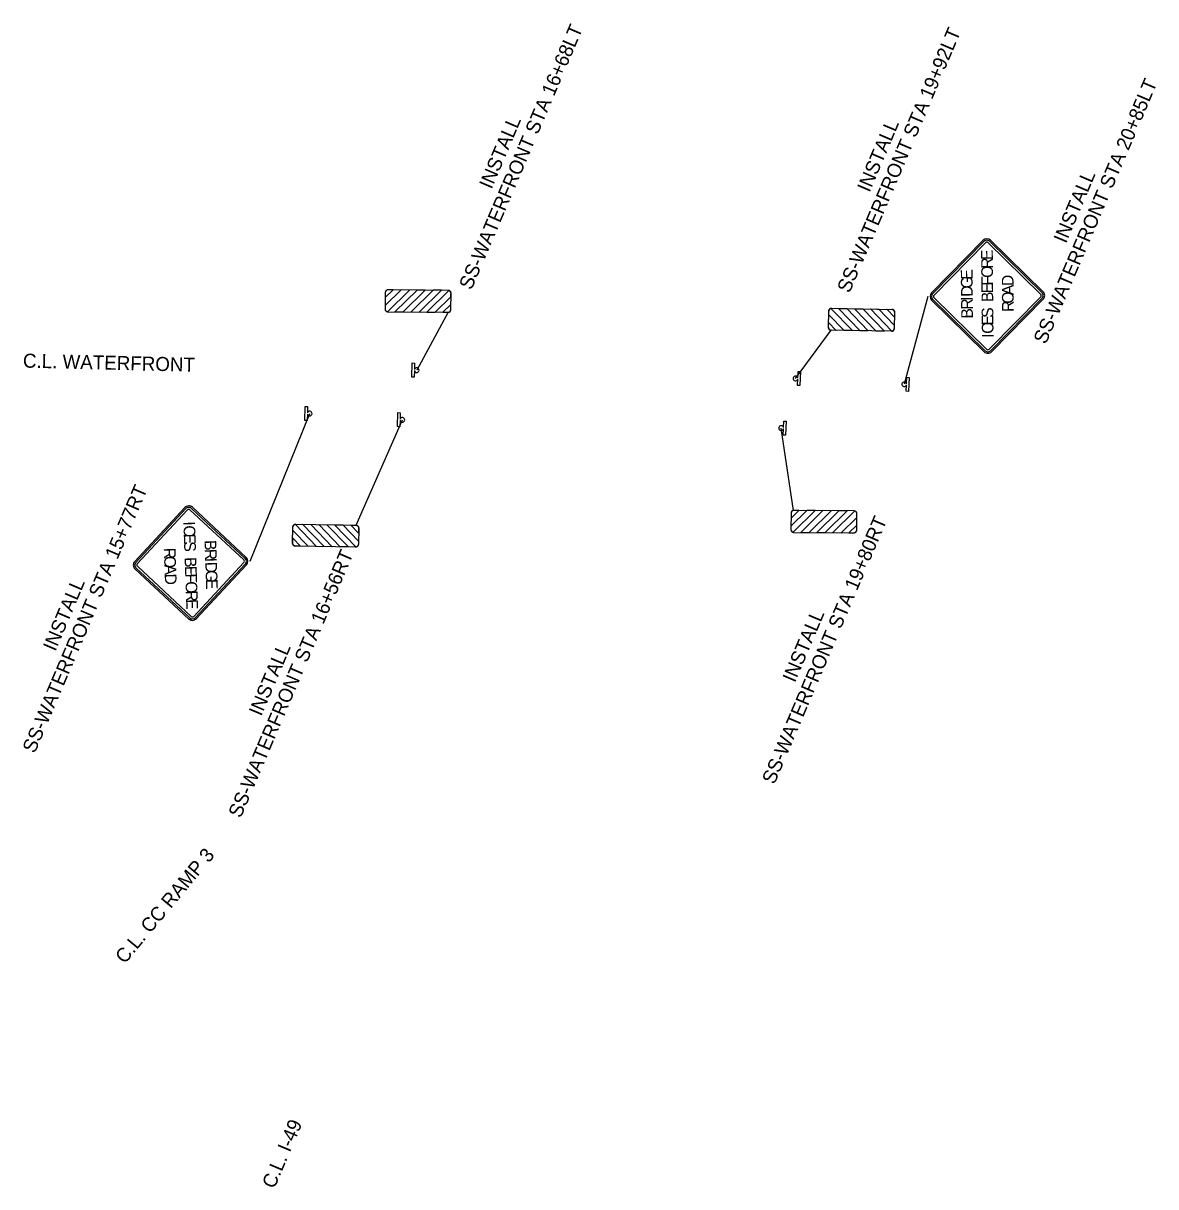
# Model space of a CAD drawing. Extents: x 639753 to 654136, y 407791 to 434220.
# Drawn here: x 652998 to 653966, y 407791 to 408786 of the extents above; entities that cross this region are included whole.
import ezdxf

# ---------------------------------------------------------------- set-up
doc = ezdxf.new("R2010")
doc.units = 0
for name, color, linetype in [('C-TRAF-SYMB', 7, 'Continuous'), ('P_SIGN_SR', 7, 'Continuous'), ('R_Anno_Text', 7, 'Continuous'), ('S_SIGN', 7, 'Continuous')]:
    doc.layers.add(name, color=color, linetype=linetype)

msp = doc.modelspace()

# ---------------------------------------------------------------- linework, layer by layer
at = {"layer": 'C-TRAF-SYMB'}
for p, q in [((653660.21, 408483.12), (653660.45, 408488.63)), ((653660.45, 408488.63), (653662.45, 408488.55)), ((653662.45, 408488.55), (653661.92, 408476.56)), ((653659.93, 408476.65), (653660.17, 408482.21)), ((653661.92, 408476.56), (653659.93, 408476.65)), ((653660.17, 408482.21), (653660.12, 408482.21)), ((653660.15, 408483.12), (653660.21, 408483.12)), ((653752.92, 408471.66), (653753.16, 408477.23)), ((653753.16, 408477.23), (653753.12, 408477.23)), ((653753.15, 408478.13), (653753.2, 408478.13)), ((653753.2, 408478.13), (653753.45, 408483.65)), ((653753.45, 408483.65), (653755.44, 408483.56)), ((653755.44, 408483.56), (653754.92, 408471.57)), ((653754.92, 408471.57), (653752.92, 408471.66)), ((653238.55, 408446.76), (653238.75, 408458.76)), ((653238.75, 408458.76), (653240.75, 408458.73)), ((653240.75, 408458.73), (653240.66, 408453.15)), ((653240.55, 408446.73), (653238.55, 408446.76)), ((653240.64, 408452.25), (653240.55, 408446.73)), ((653240.7, 408452.25), (653240.64, 408452.25)), ((653240.66, 408453.15), (653240.7, 408453.15)), ((653647.62, 408434.16), (653647.87, 408439.72)), ((653647.87, 408439.72), (653647.82, 408439.73)), ((653647.85, 408440.63), (653647.91, 408440.63)), ((653647.91, 408440.63), (653648.15, 408446.15)), ((653648.15, 408446.15), (653650.15, 408446.06)), ((653650.15, 408446.06), (653649.62, 408434.07)), ((653649.62, 408434.07), (653647.62, 408434.16))]:
    msp.add_line(p, q, dxfattribs=at)
for centre, start, end in [((653658.19, 408482.73), 87.48603, 345.16613), ((653658.19, 408482.73), 11.34816, 87.48603), ((653751.19, 408477.74), 87.48603, 345.16613), ((653751.19, 408477.74), 11.34816, 87.48603), ((653242.65, 408452.69), 269.01966, 166.69976), ((653242.65, 408452.69), 192.88179, 269.01966), ((653645.89, 408440.24), 87.48603, 345.16613), ((653645.89, 408440.24), 11.34816, 87.48603)]:
    msp.add_arc(centre, 2, start, end, dxfattribs=at)
at = {"layer": 'P_SIGN_SR'}
for p, q in [((653361.11, 408539.29), (653334.16, 408489.76)), ((653658.19, 408482.73), (653688.61, 408523.91)), ((653329.96, 408483.9), (653330.37, 408495.89)), ((653330.37, 408495.89), (653332.37, 408495.83)), ((653332.15, 408489.35), (653331.96, 408483.83)), ((653332.21, 408489.35), (653332.15, 408489.35)), ((653332.37, 408495.83), (653332.18, 408490.26)), ((653332.18, 408490.26), (653332.22, 408490.25)), ((653331.96, 408483.83), (653329.96, 408483.9)), ((653282.43, 408357.17), (653321.88, 408447.3)), ((653317.68, 408441.44), (653318.09, 408453.43)), ((653318.09, 408453.43), (653320.09, 408453.36)), ((653319.87, 408446.89), (653319.68, 408441.37)), ((653319.93, 408446.89), (653319.87, 408446.89)), ((653320.09, 408453.36), (653319.9, 408447.79)), ((653319.9, 408447.79), (653319.94, 408447.79)), ((653319.68, 408441.37), (653317.68, 408441.44)), ((653656.53, 408369.8), (653645.89, 408440.24))]:
    msp.add_line(p, q, dxfattribs=at)
for points in [[(653307.16, 408544.98), (653307.15, 408544.47), (653307.15, 408543.95), (653307.15, 408543.45), (653307.15, 408542.93), (653307.14, 408542.43), (653307.13, 408541.93), (653307.21, 408541.47), (653307.38, 408541.02), (653307.65, 408540.59), (653307.99, 408540.26), (653308.12, 408540.16), (653308.23, 408540.08), (653308.35, 408540.02), (653308.44, 408539.96), (653308.56, 408539.92), (653308.67, 408539.86), (653308.8, 408539.84), (653308.9, 408539.81), (653309, 408539.77), (653309.06, 408539.76), (653327.9, 408558.32), (653320.81, 408558.38), (653307.16, 408544.98)], [(653307.25, 408556.15), (653307.13, 408542.09)], [(653309.39, 408558.48), (653309.1, 408558.42), (653308.82, 408558.35), (653308.49, 408558.2), (653308.19, 408558.01), (653307.96, 408557.82), (653307.78, 408557.61), (653307.58, 408557.34), (653307.45, 408557.07), (653307.36, 408556.82), (653307.27, 408556.52), (653307.25, 408556), (653307.25, 408555.55), (653307.24, 408555.07), (653307.24, 408554.61), (653307.24, 408554.13), (653307.23, 408553.68), (653307.23, 408553.2), (653307.21, 408552.76), (653307.22, 408552.28), (653307.22, 408551.79), (653314.02, 408558.44), (653309.39, 408558.48)], [(653307.25, 408556.15), (653307.25, 408556.15), (653307.25, 408556.15)], [(653361.17, 408558.04), (653309.61, 408558.47)], [(653334.49, 408558.26), (653315.56, 408539.68), (653322.6, 408539.62), (653341.52, 408558.2), (653334.49, 408558.26)], [(653329.4, 408539.56), (653336.3, 408539.5), (653355.28, 408558.08), (653348.18, 408558.14), (653329.4, 408539.56)], [(653362.63, 408557.5), (653362.45, 408557.65), (653362.25, 408557.75), (653362.04, 408557.86), (653361.81, 408557.94), (653361.7, 408557.98), (653342.91, 408539.45), (653350.02, 408539.39), (653363.45, 408552.53), (653363.46, 408552.96), (653363.47, 408553.4), (653363.47, 408553.81), (653363.48, 408554.2), (653363.47, 408554.66), (653363.48, 408555.08), (653363.49, 408555.52), (653363.48, 408555.97), (653363.4, 408556.37), (653363.24, 408556.73), (653363.13, 408556.95), (653362.96, 408557.17), (653362.82, 408557.34), (653362.63, 408557.5)], [(653363.4, 408545.92), (653356.64, 408539.33), (653361.11, 408539.29), (653361.58, 408539.35), (653361.87, 408539.46), (653362.17, 408539.59), (653362.46, 408539.78), (653362.66, 408539.97), (653362.88, 408540.21), (653363.03, 408540.43), (653363.16, 408540.7), (653363.28, 408541), (653363.35, 408541.3), (653363.37, 408541.73), (653363.37, 408542.18), (653363.37, 408542.64), (653363.38, 408543.15), (653363.38, 408543.61), (653363.39, 408544.12), (653363.39, 408544.58), (653363.39, 408545.08), (653363.4, 408545.5), (653363.4, 408545.92)], [(653363.37, 408541.62), (653363.49, 408555.68)], [(653309.45, 408539.73), (653361.01, 408539.29)], [(653686.41, 408526.29), (653686.65, 408540.35)], [(653687.56, 408542.15), (653687.75, 408542.29), (653687.94, 408542.39), (653688.16, 408542.5), (653688.38, 408542.57), (653688.5, 408542.6), (653706.81, 408523.6), (653699.7, 408523.72), (653686.61, 408537.2), (653686.61, 408537.63), (653686.61, 408538.07), (653686.63, 408538.48), (653686.63, 408538.87), (653686.64, 408539.33), (653686.65, 408539.75), (653686.65, 408540.19), (653686.67, 408540.64), (653686.76, 408541.04), (653686.93, 408541.39), (653687.04, 408541.61), (653687.21, 408541.82), (653687.36, 408542), (653687.56, 408542.15)], [(653689.03, 408542.65), (653740.58, 408541.77)], [(653720.32, 408523.37), (653713.42, 408523.48), (653694.92, 408542.54), (653702.02, 408542.42), (653720.32, 408523.37)], [(653715.71, 408542.19), (653734.16, 408523.13), (653727.12, 408523.25), (653708.68, 408542.3), (653715.71, 408542.19)], [(653742.69, 408528.22), (653742.69, 408527.71), (653742.67, 408527.18), (653742.66, 408526.69), (653742.65, 408526.17), (653742.65, 408525.66), (653742.64, 408525.17), (653742.55, 408524.7), (653742.37, 408524.26), (653742.08, 408523.84), (653741.74, 408523.52), (653741.61, 408523.43), (653741.49, 408523.34), (653741.37, 408523.29), (653741.28, 408523.23), (653741.16, 408523.19), (653741.05, 408523.14), (653740.92, 408523.12), (653740.82, 408523.09), (653740.72, 408523.06), (653740.66, 408523.05), (653722.3, 408542.08), (653729.38, 408541.96), (653742.69, 408528.22)], [(653740.81, 408541.76), (653741.09, 408541.7), (653741.37, 408541.62), (653741.7, 408541.47), (653741.99, 408541.26), (653742.21, 408541.07), (653742.39, 408540.86), (653742.58, 408540.58), (653742.71, 408540.31), (653742.8, 408540.06), (653742.87, 408539.76), (653742.88, 408539.23), (653742.87, 408538.78), (653742.87, 408538.3), (653742.86, 408537.84), (653742.85, 408537.37), (653742.84, 408536.92), (653742.83, 408536.44), (653742.83, 408535.99), (653742.82, 408535.51), (653742.81, 408535.03), (653736.18, 408541.84), (653740.81, 408541.76)], [(653742.89, 408539.38), (653742.65, 408525.33)], [(653742.89, 408539.38), (653742.89, 408539.38), (653742.89, 408539.38)], [(653686.5, 408530.59), (653693.09, 408523.83), (653688.61, 408523.91), (653688.14, 408523.98), (653687.85, 408524.09), (653687.56, 408524.23), (653687.28, 408524.43), (653687.08, 408524.63), (653686.87, 408524.87), (653686.72, 408525.1), (653686.6, 408525.37), (653686.49, 408525.67), (653686.43, 408525.97), (653686.42, 408526.4), (653686.43, 408526.85), (653686.43, 408527.31), (653686.44, 408527.82), (653686.45, 408528.28), (653686.46, 408528.79), (653686.47, 408529.25), (653686.48, 408529.75), (653686.49, 408530.17), (653686.5, 408530.59)], [(653740.26, 408523.02), (653688.71, 408523.9)], [(653654.29, 408356.31), (653654.29, 408355.8), (653654.29, 408355.27), (653654.29, 408354.78), (653654.29, 408354.26), (653654.27, 408353.76), (653654.27, 408353.26), (653654.35, 408352.79), (653654.52, 408352.34), (653654.79, 408351.91), (653655.12, 408351.59), (653655.25, 408351.49), (653655.37, 408351.41), (653655.49, 408351.35), (653655.58, 408351.29), (653655.7, 408351.25), (653655.81, 408351.19), (653655.94, 408351.17), (653656.04, 408351.14), (653656.14, 408351.1), (653656.2, 408351.09), (653675.03, 408369.65), (653667.95, 408369.71), (653654.29, 408356.31)], [(653654.39, 408367.48), (653654.27, 408353.42)], [(653656.53, 408369.8), (653656.24, 408369.75), (653655.96, 408369.68), (653655.63, 408369.53), (653655.33, 408369.33), (653655.1, 408369.15), (653654.92, 408368.94), (653654.72, 408368.66), (653654.59, 408368.4), (653654.49, 408368.15), (653654.41, 408367.85), (653654.39, 408367.32), (653654.38, 408366.88), (653654.38, 408366.4), (653654.38, 408365.94), (653654.37, 408365.46), (653654.37, 408365.01), (653654.37, 408364.53), (653654.35, 408364.08), (653654.35, 408363.6), (653654.36, 408363.12), (653661.15, 408369.76), (653656.53, 408369.8)], [(653654.39, 408367.48), (653654.39, 408367.48), (653654.39, 408367.48)], [(653708.3, 408369.37), (653656.75, 408369.8)], [(653681.63, 408369.59), (653662.69, 408351.01), (653669.74, 408350.95), (653688.66, 408369.52), (653681.63, 408369.59)], [(653676.54, 408350.89), (653683.44, 408350.83), (653702.42, 408369.41), (653695.32, 408369.47), (653676.54, 408350.89)], [(653709.77, 408368.83), (653709.58, 408368.97), (653709.39, 408369.08), (653709.18, 408369.19), (653708.95, 408369.27), (653708.83, 408369.31), (653690.05, 408350.78), (653697.16, 408350.71), (653710.59, 408363.86), (653710.6, 408364.29), (653710.61, 408364.73), (653710.61, 408365.14), (653710.62, 408365.52), (653710.61, 408365.99), (653710.62, 408366.41), (653710.62, 408366.85), (653710.62, 408367.3), (653710.54, 408367.7), (653710.38, 408368.06), (653710.27, 408368.27), (653710.1, 408368.49), (653709.96, 408368.67), (653709.77, 408368.83)], [(653710.51, 408352.94), (653710.63, 408367)], [(653229.18, 408357.55), (653229.37, 408357.69), (653229.57, 408357.79), (653229.78, 408357.9), (653230.01, 408357.97), (653230.13, 408358.01), (653248.44, 408339.01), (653241.32, 408339.12), (653228.23, 408352.6), (653228.24, 408353.04), (653228.24, 408353.47), (653228.25, 408353.89), (653228.25, 408354.27), (653228.27, 408354.73), (653228.27, 408355.16), (653228.28, 408355.59), (653228.3, 408356.04), (653228.38, 408356.45), (653228.56, 408356.8), (653228.67, 408357.01), (653228.84, 408357.23), (653228.99, 408357.4), (653229.18, 408357.55)], [(653230.66, 408358.05), (653282.21, 408357.17)], [(653261.94, 408338.77), (653255.04, 408338.88), (653236.55, 408357.94), (653243.64, 408357.83), (653261.94, 408338.77)], [(653257.33, 408357.6), (653275.79, 408338.54), (653268.74, 408338.65), (653250.31, 408357.71), (653257.33, 408357.6)], [(653284.32, 408343.62), (653284.31, 408343.12), (653284.3, 408342.59), (653284.28, 408342.09), (653284.27, 408341.57), (653284.28, 408341.07), (653284.27, 408340.57), (653284.18, 408340.11), (653283.99, 408339.66), (653283.71, 408339.24), (653283.37, 408338.93), (653283.24, 408338.83), (653283.12, 408338.75), (653283, 408338.7), (653282.91, 408338.64), (653282.79, 408338.6), (653282.68, 408338.54), (653282.55, 408338.52), (653282.45, 408338.5), (653282.34, 408338.46), (653282.28, 408338.45), (653263.93, 408357.49), (653271.01, 408357.36), (653284.32, 408343.62)], [(653282.43, 408357.17), (653282.72, 408357.11), (653283, 408357.03), (653283.32, 408356.87), (653283.61, 408356.67), (653283.84, 408356.48), (653284.02, 408356.27), (653284.21, 408355.98), (653284.33, 408355.71), (653284.42, 408355.46), (653284.5, 408355.16), (653284.51, 408354.64), (653284.5, 408354.19), (653284.49, 408353.71), (653284.48, 408353.25), (653284.47, 408352.77), (653284.46, 408352.32), (653284.46, 408351.84), (653284.46, 408351.39), (653284.45, 408350.92), (653284.43, 408350.43), (653277.81, 408357.25), (653282.43, 408357.17)], [(653710.54, 408357.25), (653703.77, 408350.66), (653708.25, 408350.62), (653708.72, 408350.68), (653709.01, 408350.78), (653709.31, 408350.92), (653709.6, 408351.11), (653709.8, 408351.3), (653710.02, 408351.54), (653710.17, 408351.76), (653710.3, 408352.03), (653710.41, 408352.33), (653710.49, 408352.63), (653710.5, 408353.06), (653710.51, 408353.5), (653710.51, 408353.97), (653710.52, 408354.48), (653710.52, 408354.94), (653710.52, 408355.45), (653710.52, 408355.91), (653710.53, 408356.4), (653710.53, 408356.83), (653710.54, 408357.25)], [(653228.04, 408341.69), (653228.28, 408355.75)], [(653284.51, 408354.79), (653284.27, 408340.73)], [(653284.51, 408354.79), (653284.51, 408354.79), (653284.51, 408354.79)], [(653656.59, 408351.05), (653708.15, 408350.62)], [(653228.12, 408346), (653234.71, 408339.24), (653230.24, 408339.31), (653229.77, 408339.38), (653229.48, 408339.5), (653229.19, 408339.64), (653228.9, 408339.83), (653228.7, 408340.03), (653228.5, 408340.28), (653228.34, 408340.5), (653228.22, 408340.77), (653228.12, 408341.07), (653228.05, 408341.37), (653228.05, 408341.8), (653228.06, 408342.25), (653228.06, 408342.71), (653228.07, 408343.23), (653228.08, 408343.69), (653228.09, 408344.2), (653228.1, 408344.66), (653228.11, 408345.15), (653228.11, 408345.57), (653228.12, 408346)], [(653281.89, 408338.43), (653230.34, 408339.31)]]:
    msp.add_lwpolyline(points, dxfattribs=at)
for centre, radius, start, end in [((653309.59, 408556.13), 2.34, 89.51837, 179.51858), ((653361.15, 408555.7), 2.34, 359.51874, 89.51837), ((653309.47, 408542.07), 2.34, 179.51858, 269.51879), ((653361.03, 408541.64), 2.34, 269.51879, 359.51843), ((653688.99, 408540.31), 2.34, 89.01981, 179.01945), ((653740.54, 408539.42), 2.34, 359.0196, 89.01981), ((653688.75, 408526.25), 2.34, 179.01976, 269.01939), ((653740.3, 408525.37), 2.34, 269.01939, 359.0196), ((653334.16, 408489.76), 2, 191.92363, 268.06151), ((653334.16, 408489.76), 2, 268.06151, 165.7416), ((653321.88, 408447.3), 2, 191.92363, 268.06151), ((653321.88, 408447.3), 2, 268.06151, 165.7416), ((653656.73, 408367.46), 2.34, 89.51837, 179.51858), ((653708.28, 408367.02), 2.34, 359.51874, 89.51837), ((653230.62, 408355.71), 2.34, 89.01981, 179.01945), ((653282.17, 408354.83), 2.34, 359.0196, 89.01981), ((653656.61, 408353.4), 2.34, 179.51858, 269.51879), ((653708.17, 408352.96), 2.34, 269.51879, 359.51843), ((653230.38, 408341.65), 2.34, 179.01976, 269.01939), ((653281.93, 408340.77), 2.34, 269.01939, 359.0196)]:
    msp.add_arc(centre, radius, start, end, dxfattribs=at)
at = {"layer": 'S_SIGN'}
for p, q in [((653818.65, 408600.87), (653774.5, 408555.94)), ((653869.96, 408556.84), (653825.02, 408600.93)), ((653771.35, 408552.73), (653751.19, 408477.74)), ((653774.56, 408549.58), (653819.51, 408505.49)), ((653825.87, 408505.55), (653870.02, 408550.48)), ((653191.65, 408326.53), (653242.65, 408452.69)), ((653135.88, 408372.24), (653092.95, 408326.14)), ((653188.35, 408329.6), (653142.24, 408372.47)), ((653093.18, 408319.79), (653139.29, 408276.92)), ((653145.65, 408277.15), (653188.58, 408323.24))]:
    msp.add_line(p, q, dxfattribs=at)
for points in [[(653819.55, 408600), (653775.4, 408555.06)], [(653776.65, 408553.84), (653820.8, 408598.77)], [(653819.55, 408600), (653819.55, 408600), (653819.55, 408600)], [(653822.92, 408598.79), (653867.86, 408554.7)], [(653869.09, 408555.95), (653824.14, 408600.04)], [(653869.09, 408555.95), (653869.09, 408555.95), (653869.09, 408555.95)], [(653775.44, 408550.47), (653820.38, 408506.38)], [(653775.44, 408550.47), (653775.44, 408550.47), (653775.44, 408550.47)], [(653821.61, 408507.63), (653776.66, 408551.72)], [(653867.88, 408552.58), (653823.73, 408507.65)], [(653824.98, 408506.43), (653869.13, 408551.36)], [(653824.98, 408506.43), (653824.98, 408506.43), (653824.98, 408506.43)], [(653136.8, 408371.39), (653093.87, 408325.29)], [(653095.15, 408324.1), (653138.08, 408370.2)], [(653136.8, 408371.39), (653136.8, 408371.39), (653136.8, 408371.39)], [(653140.2, 408370.27), (653186.31, 408327.4)], [(653187.5, 408328.68), (653141.39, 408371.55)], [(653187.5, 408328.68), (653187.5, 408328.68), (653187.5, 408328.68)], [(653094.03, 408320.7), (653140.14, 408277.83)], [(653094.03, 408320.7), (653094.03, 408320.7), (653094.03, 408320.7)], [(653141.34, 408279.11), (653095.23, 408321.98)], [(653186.38, 408325.28), (653143.45, 408279.19)], [(653144.74, 408278), (653187.67, 408324.09)], [(653144.74, 408278), (653144.74, 408278), (653144.74, 408278)]]:
    msp.add_lwpolyline(points, dxfattribs=at)
for centre, major_axis, start_param, end_param in [((653821.86, 408597.72), (-4.33, -1.22), 3.661235, 5.232025), ((653821.86, 408597.72), (-3.13, -0.88), 3.661235, 5.232025), ((653821.86, 408597.72), (-1.44, -0.41), 3.661235, 5.232025), ((653777.72, 408552.79), (-4.33, -1.22), 5.232028, 6.80282), ((653866.81, 408553.63), (-3.13, -0.88), 2.090435, 3.661235), ((653866.81, 408553.63), (-4.33, -1.22), 2.090435, 3.661235), ((653777.72, 408552.79), (-3.13, -0.88), 5.232028, 6.80282), ((653777.72, 408552.79), (-1.44, -0.41), 5.232028, 6.80282), ((653866.81, 408553.63), (-1.44, -0.41), 2.090435, 3.661235), ((653822.66, 408508.7), (-3.13, -0.88), 0.519635, 2.090435), ((653822.66, 408508.7), (-1.44, -0.41), 0.519635, 2.090435), ((653822.66, 408508.7), (-4.33, -1.22), 0.519635, 2.090435), ((653139.18, 408369.18), (4.3, 1.34), 0.519635, 2.090435), ((653139.18, 408369.18), (3.1, 0.97), 0.519635, 2.090435), ((653139.18, 408369.18), (1.43, 0.45), 0.519635, 2.090435), ((653185.29, 408326.3), (1.43, 0.45), 5.232028, 6.80282), ((653185.29, 408326.3), (3.1, 0.97), 5.232028, 6.80282), ((653185.29, 408326.3), (4.3, 1.34), 5.232028, 6.80282), ((653096.25, 408323.08), (4.3, 1.34), 2.090435, 3.661235), ((653096.25, 408323.08), (3.1, 0.97), 2.090435, 3.661235), ((653096.25, 408323.08), (1.43, 0.45), 2.090435, 3.661235), ((653142.36, 408280.21), (3.1, 0.97), 3.661235, 5.232025), ((653142.36, 408280.21), (1.43, 0.45), 3.661235, 5.232025), ((653142.36, 408280.21), (4.3, 1.34), 3.661235, 5.232025)]:
    msp.add_ellipse(centre, major_axis=major_axis, ratio=0.99903, start_param=start_param, end_param=end_param, dxfattribs=at)

# ---------------------------------------------------------------- texts
at = {"layer": 'R_Anno_Text'}
for s, rotation, p in [('SS-WATERFRONT STA 16+68LT', 66.91246, (653380.93, 408557.76)), ('SS-WATERFRONT STA 19+92LT', 66.91246, (653704.29, 408554.99)), ('SS-WATERFRONT STA 20+85LT', 66.91246, (653872.29, 408511.32)), ('INSTALL', 66.91246, (653398.12, 408643.98)), ('INSTALL', 66.91246, (653721.47, 408641.21)), ('INSTALL', 66.91246, (653889.48, 408597.53)), ('C.L. WATERFRONT', 358.58687, (652997.23, 408492)), ('SS-WATERFRONT STA 15+77RT', 66.91246, (653007.48, 408161.47)), ('SS-WATERFRONT STA 19+80RT', 66.91246, (653640.07, 408134.76)), ('SS-WATERFRONT STA 16+56RT', 66.91246, (653183.57, 408106.04)), ('INSTALL', 66.91246, (653025.06, 408248.62)), ('INSTALL', 66.91246, (653657.65, 408221.91)), ('INSTALL', 66.91246, (653201.15, 408193.18)), ('C.L. CC RAMP 3', 50.29452, (653084.44, 407981.34)), ('C.L. I-49', 66.91246, (653212.38, 407788.96))]:
    msp.add_text(s, height=12, rotation=rotation, dxfattribs=at).set_placement(p)
at = {"layer": 'S_SIGN'}
for s, rotation, p in [('E', 90.51274, (653826.99, 408584.04)), ('O', 90.51274, (653827.12, 408568.77)), ('R', 90.51274, (653827.05, 408576.56)), ('G', 90.51274, (653809.7, 408559.69)), ('E', 90.51274, (653809.64, 408567.24)), ('F', 90.51274, (653827.18, 408562.15)), ('D', 90.51274, (653844.69, 408561.75)), ('D', 90.51274, (653809.77, 408552.55)), ('E', 90.51274, (653827.24, 408555.54)), ('B', 90.51274, (653827.31, 408548.05)), ('O', 90.51274, (653844.82, 408546.64)), ('A', 90.51274, (653844.76, 408553.96)), ('I', 90.51274, (653809.8, 408549.05)), ('R', 90.51274, (653809.87, 408541.5)), ('R', 90.51274, (653844.89, 408539.63)), ('B', 90.51274, (653809.93, 408533.95)), ('S', 90.51274, (653827.43, 408534.6)), ('E', 90.51274, (653827.49, 408527.98)), ('C', 90.51274, (653827.55, 408520.9)), ('I', 90.51274, (653827.58, 408517.48)), ('I', 272.04613, (653134.49, 408360.27)), ('C', 272.04613, (653134.62, 408356.85)), ('E', 272.04613, (653134.87, 408349.77)), ('R', 272.04613, (653117.79, 408337.66)), ('S', 272.04613, (653135.1, 408343.16)), ('B', 272.04613, (653152.58, 408344.27)), ('O', 272.04613, (653118.04, 408330.66)), ('B', 272.04613, (653135.58, 408329.71)), ('R', 272.04613, (653152.85, 408336.73)), ('I', 272.04613, (653153.12, 408329.18)), ('A', 272.04613, (653118.3, 408323.34)), ('E', 272.04613, (653135.85, 408322.23)), ('D', 272.04613, (653153.24, 408325.69)), ('G', 272.04613, (653153.49, 408318.56)), ('D', 272.04613, (653118.58, 408315.55)), ('F', 272.04613, (653136.09, 408315.62)), ('O', 272.04613, (653136.32, 408309.01)), ('E', 272.04613, (653153.76, 408311.01)), ('R', 272.04613, (653136.6, 408301.22)), ('E', 272.04613, (653136.87, 408293.74))]:
    msp.add_text(s, height=10, rotation=rotation, dxfattribs=at).set_placement(p)

doc.saveas('drawing.dxf')
